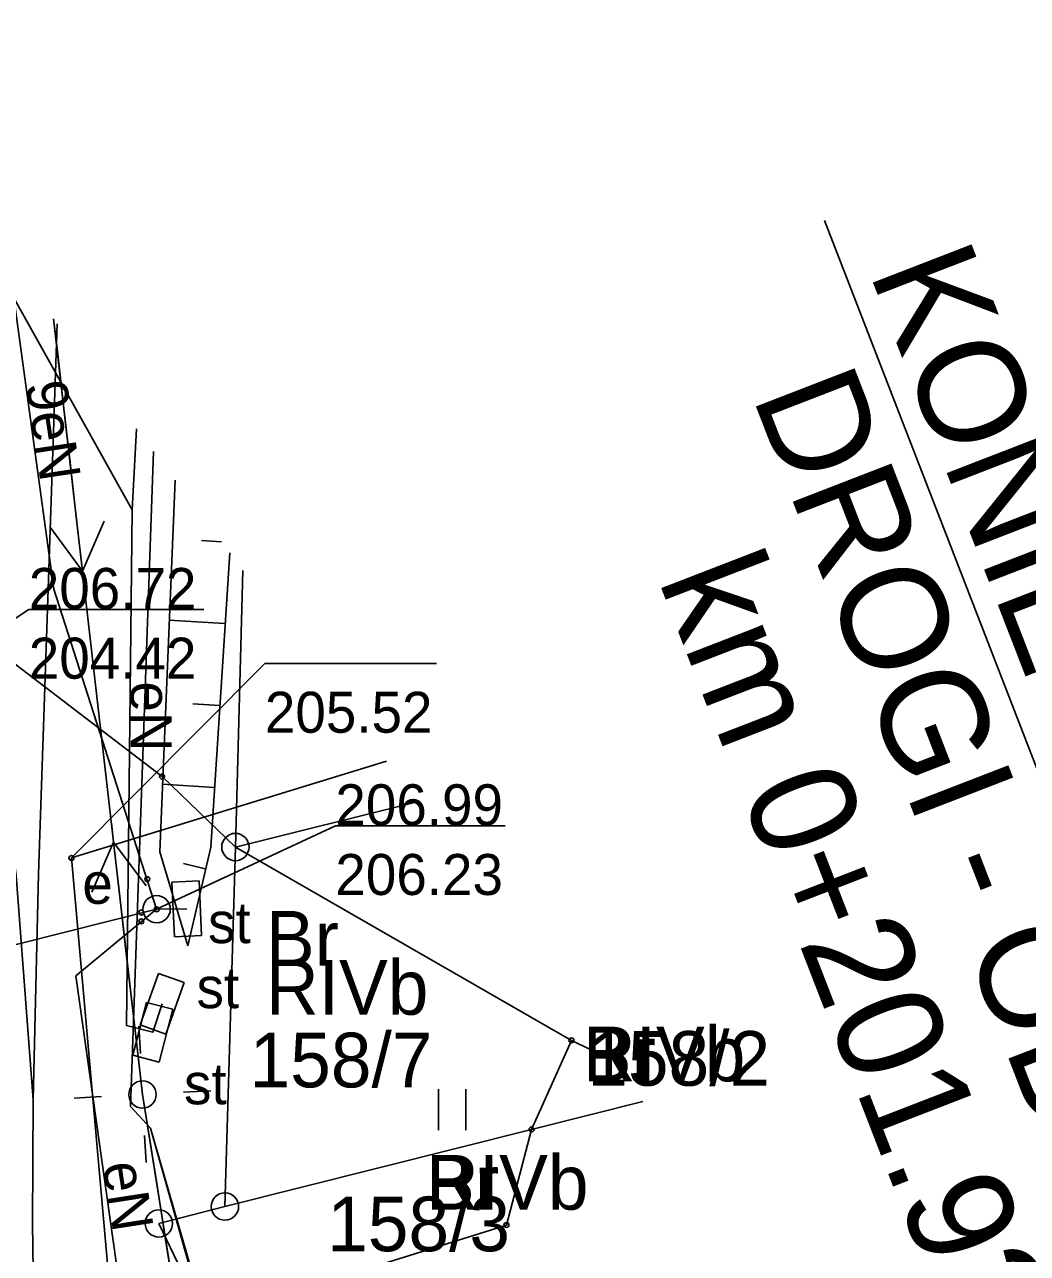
# Model space of a CAD drawing. Extents: x 6512606 to 6513006, y 6022524 to 6022728.
# Drawn here: x 6512853.97 to 6512872.32, y 6022634.38 to 6022656.88 of the extents above; entities that cross this region are included whole.
import ezdxf

# ---------------------------------------------------------------- set-up
doc = ezdxf.new("R2010")
doc.units = 0
for name, color, linetype in [('202-punkt graniczny', 7, 'Continuous'), ('203-punkt graniczny', 7, 'Continuous'), ('209-oznaczenie konturu klasyfikacyjnego', 7, 'Continuous'), ('210-oznaczenie konturu użytku gruntowego', 7, 'Continuous'), ('211-numer działki ewidencyjnej', 7, 'Continuous'), ('217-kontur klasyfikacyjny', 7, 'Continuous'), ('218-kontur użytku gruntowego', 7, 'Continuous'), ('219-działka ewidencyjna', 7, 'Continuous'), ('4', 7, 'Continuous'), ('820-Skarpa nieumocniona', 7, 'Continuous'), ('823-Szczyt skarpy nieumocninej', 7, 'Continuous'), ('824-Podnóże skarpy nieumocninej', 7, 'Continuous'), ('940-Trawnik symb. poj.', 7, 'Continuous'), ('chodnik (powierzchnia)', 7, 'Continuous'), ('Default', 7, 'Continuous'), ('krawężnik (linia)', 7, 'Continuous'), ('latarnia na słupie lub maszcie (punkt)', 7, 'Continuous'), ('maxp_opisy', 7, 'Continuous'), ('ogrodzenie trwałe (linia)', 7, 'Continuous'), ('przewód elektroenergetyczny (linia)', 7, 'Continuous'), ('przewód elektroenergetyczny (linia)-Atr1', 7, 'Continuous'), ('przewód elektroenergetyczny niskiego napięcia (linia)', 7, 'Continuous'), ('przewód elektroenergetyczny niskiego napięcia (linia) - symbol', 7, 'Continuous'), ('przewód gazowy (linia)', 7, 'Continuous'), ('punkt o określonej wysokości (sieć ciepłownicza)-Atr2', 7, 'Continuous'), ('punkt o określonej wysokości (sieć ciepłownicza)-Atr3', 7, 'Continuous'), ('punkt o określonej wysokości (sieć elektroenergetyczna)', 7, 'Continuous'), ('punkt o określonej wysokości (sieć elektroenergetyczna)-Atr2', 7, 'Continuous'), ('punkt o określonej wysokości (sieć elektroenergetyczna)-Atr3', 7, 'Continuous'), ('punkt o określonej wysokości (sieć gazowa)', 7, 'Continuous'), ('punkt o określonej wysokości (sieć gazowa)-Atr2', 7, 'Continuous'), ('punkt o określonej wysokości (sieć gazowa)-Atr3', 7, 'Continuous'), ('szafa elektroenergetyczna (punkt)', 7, 'Continuous'), ('szafa elektroenergetyczna (punkt)-Atr17', 7, 'Continuous'), ('słup (punkt)', 7, 'Continuous'), ('właz okrągły - siec elektroenergetyczna (punkt)', 7, 'Continuous'), ('właz okrągły - siec elektroenergetyczna (punkt)-Atr17', 7, 'Continuous')]:
    doc.layers.add(name, color=color, linetype=linetype)

# ---------------------------------------------------------------- blocks, each defined once
blk = doc.blocks.new('203')
at = {"layer": 'Default'}
blk.add_circle((0, 0), 0.45, dxfattribs=at)
blk = doc.blocks.new('202')
at = {"layer": 'Default'}
blk.add_circle((0, 0), 2.5, dxfattribs=at)
blk = doc.blocks.new('940P')
at = {"layer": 'Default'}
for p, q in [((-2.5, -3.75), (-2.5, 3.75)), ((2.5, -3.75), (2.5, 3.75))]:
    blk.add_line(p, q, dxfattribs=at)
blk = doc.blocks.new('US18')
at = {"layer": 'Default'}
for p, q in [((-5, -2.5), (-5, 2.5)), ((-5, 2.5), (5, 2.5)), ((5, -2.5), (5, 2.5)), ((-5, -2.5), (5, -2.5))]:
    blk.add_line(p, q, dxfattribs=at)
blk = doc.blocks.new('PW01')
at = {"layer": 'Default'}
blk.add_circle((0, 0), 0.45, dxfattribs=at)
blk = doc.blocks.new('US22')
at = {"layer": 'Default'}
blk.add_circle((0, 0), 2.5, dxfattribs=at)
blk = doc.blocks.new('PE04')
at = {"layer": 'Default'}
for p, q in [((46.5, 0), (37.84, 5)), ((6.5, 0), (0, 0)), ((6.5, 0), (16.5, 0)), ((16.5, 0), (26.5, 0)), ((26.5, 0), (36.5, 0)), ((36.5, 0), (46.5, 0)), ((46.5, 0), (37.84, -5)), ((46.5, 0), (50, 0))]:
    blk.add_line(p, q, dxfattribs=at)
blk = doc.blocks.new('SM04')
at = {"layer": 'Default'}
blk.add_circle((0, 0), 2.5, dxfattribs=at)
blk = doc.blocks.new('SM011')
at = {"layer": 'Default'}
for p, q in [((-5.3, 5.31), (-8.83, 8.84)), ((5.31, 5.31), (8.84, 8.84)), ((-5.3, -5.3), (-8.83, -8.83)), ((5.31, -5.3), (8.84, -8.83))]:
    blk.add_line(p, q, dxfattribs=at)

msp = doc.modelspace()

# ---------------------------------------------------------------- linework, layer by layer
at = {"layer": '217-kontur klasyfikacyjny'}
for points in [[(6512857.83, 6022641.82), (6512857.64, 6022635.24)], [(6512863.98, 6022638.28), (6512857.83, 6022641.82)], [(6512863.98, 6022638.28), (6512863.25, 6022636.65)], [(6512863.25, 6022636.65), (6512863.98, 6022638.28)], [(6512864.702, 6022637.935), (6512863.98, 6022638.28)], [(6512865.286, 6022637.159), (6512863.25, 6022636.65)], [(6512863.25, 6022636.65), (6512865.286, 6022637.159)], [(6512863.25, 6022636.65), (6512857.64, 6022635.24)], [(6512857.64, 6022635.24), (6512863.25, 6022636.65)], [(6512863.25, 6022636.65), (6512862.79, 6022634.9)], [(6512862.79, 6022634.9), (6512863.25, 6022636.65)], [(6512857.64, 6022635.24), (6512856.43, 6022634.93)], [(6512856.43, 6022634.93), (6512857.27, 6022633.17)], [(6512862.79, 6022634.9), (6512857.27, 6022633.17)], [(6512857.27, 6022633.17), (6512862.79, 6022634.9)]]:
    msp.add_lwpolyline(points, dxfattribs=at)
at = {"layer": '218-kontur użytku gruntowego'}
for points in [[(6512838.55, 6022656.82), (6512856.49, 6022643.11)], [(6512856.49, 6022643.11), (6512838.55, 6022656.82)], [(6512857.83, 6022641.82), (6512857.969, 6022646.885)], [(6512857.969, 6022646.885), (6512857.83, 6022641.82)], [(6512856.49, 6022643.11), (6512857.83, 6022641.82)], [(6512857.83, 6022641.82), (6512856.49, 6022643.11)], [(6512857.64, 6022635.24), (6512857.83, 6022641.82)], [(6512857.83, 6022641.82), (6512857.64, 6022635.24)], [(6512863.98, 6022638.28), (6512857.83, 6022641.82)], [(6512857.83, 6022641.82), (6512863.98, 6022638.28)], [(6512863.98, 6022638.28), (6512863.25, 6022636.65)], [(6512863.25, 6022636.65), (6512863.98, 6022638.28)], [(6512864.702, 6022637.935), (6512863.98, 6022638.28)], [(6512863.98, 6022638.28), (6512864.702, 6022637.935)], [(6512865.286, 6022637.159), (6512863.25, 6022636.65)], [(6512863.25, 6022636.65), (6512865.286, 6022637.159)], [(6512863.25, 6022636.65), (6512857.64, 6022635.24)], [(6512857.64, 6022635.24), (6512863.25, 6022636.65)], [(6512863.25, 6022636.65), (6512862.79, 6022634.9)], [(6512862.79, 6022634.9), (6512863.25, 6022636.65)], [(6512856.43, 6022634.93), (6512857.64, 6022635.24)], [(6512857.64, 6022635.24), (6512856.43, 6022634.93)], [(6512857.27, 6022633.17), (6512856.43, 6022634.93)], [(6512856.43, 6022634.93), (6512857.27, 6022633.17)], [(6512862.79, 6022634.9), (6512857.27, 6022633.17)], [(6512857.27, 6022633.17), (6512862.79, 6022634.9)]]:
    msp.add_lwpolyline(points, dxfattribs=at)
at = {"layer": '219-działka ewidencyjna'}
for points in [[(6512856.49, 6022643.11), (6512838.55, 6022656.82)], [(6512857.83, 6022641.82), (6512857.969, 6022646.885)], [(6512857.83, 6022641.82), (6512856.49, 6022643.11)], [(6512857.83, 6022641.82), (6512861.155, 6022642.649)], [(6512857.83, 6022641.82), (6512857.64, 6022635.24)], [(6512863.98, 6022638.28), (6512857.83, 6022641.82)], [(6512863.98, 6022638.28), (6512863.25, 6022636.65)], [(6512864.702, 6022637.935), (6512863.98, 6022638.28)], [(6512865.286, 6022637.159), (6512863.25, 6022636.65)], [(6512863.25, 6022636.65), (6512857.64, 6022635.24)], [(6512863.25, 6022636.65), (6512862.79, 6022634.9)], [(6512856.43, 6022634.93), (6512857.64, 6022635.24)], [(6512857.27, 6022633.17), (6512856.43, 6022634.93)], [(6512862.79, 6022634.9), (6512857.27, 6022633.17)]]:
    msp.add_lwpolyline(points, dxfattribs=at)
at = {"layer": '4'}
for points in [[(6512856.49, 6022643.11), (6512838.55, 6022656.82)], [(6512857.83, 6022641.82), (6512857.969, 6022646.885)], [(6512857.83, 6022641.82), (6512856.49, 6022643.11)], [(6512857.83, 6022641.82), (6512861.155, 6022642.649)], [(6512857.83, 6022641.82), (6512857.64, 6022635.24)], [(6512863.98, 6022638.28), (6512857.83, 6022641.82)], [(6512863.98, 6022638.28), (6512863.25, 6022636.65)], [(6512864.702, 6022637.935), (6512863.98, 6022638.28)], [(6512865.286, 6022637.159), (6512863.25, 6022636.65)], [(6512863.25, 6022636.65), (6512857.64, 6022635.24)], [(6512863.25, 6022636.65), (6512862.79, 6022634.9)], [(6512856.43, 6022634.93), (6512857.64, 6022635.24)], [(6512857.27, 6022633.17), (6512856.43, 6022634.93)], [(6512862.79, 6022634.9), (6512857.27, 6022633.17)]]:
    msp.add_lwpolyline(points, dxfattribs=at)
at = {"layer": '820-Skarpa nieumocniona'}
for p, q in [((6512857.575, 6022647.409), (6512857.21, 6022647.43)), ((6512857.64, 6022645.91), (6512856.61, 6022645.97)), ((6512857.54, 6022644.41), (6512857.05, 6022644.44)), ((6512857.45, 6022642.91), (6512856.49, 6022642.97)), ((6512857.28, 6022641.42), (6512856.88, 6022641.52))]:
    msp.add_line(p, q, dxfattribs=at)
at = {"layer": '823-Szczyt skarpy nieumocninej'}
msp.add_lwpolyline([(6512857.727, 6022647.206), (6512857.38, 6022641.82), (6512856.96, 6022640.01)], dxfattribs=at)
at = {"layer": '824-Podnóże skarpy nieumocninej'}
msp.add_lwpolyline([(6512856.728, 6022648.534), (6512856.45, 6022641.73), (6512856.96, 6022640.01)], dxfattribs=at)
at = {"layer": 'chodnik (powierzchnia)'}
for points in [[(6512852.028, 6022654.782), (6512852.46, 6022651.24), (6512853.17, 6022646.34), (6512853.82, 6022641.3), (6512854.13, 6022637.19), (6512854.23, 6022641.33)], [(6512854.23, 6022641.33), (6512854.572, 6022651.4)], [(6512856.331, 6022649.061), (6512855.91, 6022637.07), (6512856.28, 6022636.67), (6512857.18, 6022633.47)]]:
    msp.add_lwpolyline(points, dxfattribs=at)
at = {"layer": 'krawężnik (linia)'}
msp.add_lwpolyline([(6512854.13, 6022634.06), (6512854.12, 6022634.93), (6512854.13, 6022637.19), (6512853.82, 6022641.3), (6512853.17, 6022646.34), (6512852.46, 6022651.24), (6512852.028, 6022654.782)], dxfattribs=at)
at = {"layer": 'maxp_opisy'}
msp.add_lwpolyline([(6512856.121, 6022593.53), (6512879.345, 6022625.572), (6512868.61, 6022653.292)], dxfattribs=at)
at = {"layer": 'ogrodzenie trwałe (linia)'}
msp.add_lwpolyline([(6512859.49, 6022628.57), (6512858.5, 6022630.69), (6512857.21, 6022633.44), (6512856.28, 6022636.67)], dxfattribs=at)
at = {"layer": 'przewód elektroenergetyczny (linia)'}
for points in [[(6512856.32, 6022638.43), (6512855.84, 6022638.55), (6512855.94, 6022647.99), (6512853.31, 6022652.69), (6512841.05, 6022650.73), (6512840.36, 6022658.31), (6512832.38, 6022663.33)], [(6512856.39, 6022640.68), (6512854.51, 6022646.54), (6512853.677, 6022652.59)], [(6512856.022, 6022649.473), (6512855.94, 6022647.99), (6512855.84, 6022638.55), (6512856.32, 6022638.43), (6512856.49, 6022638.95)], [(6512856.39, 6022640.68), (6512852.99, 6022639.83), (6512851.54, 6022639.74), (6512850.48, 6022647.67), (6512851.95, 6022647.83), (6512852.99, 6022639.83)], [(6512856.39, 6022640.68), (6512852.99, 6022639.83), (6512851.54, 6022639.74), (6512849.57, 6022639.5), (6512850.08, 6022635.56), (6512848.6, 6022635.43), (6512846.66, 6022647.32), (6512848.47, 6022647.49), (6512849.57, 6022639.5)], [(6512856.39, 6022640.68), (6512854.91, 6022639.46), (6512857.58, 6022620.49)], [(6512856.39, 6022640.68), (6512856.94, 6022640.69)]]:
    msp.add_lwpolyline(points, dxfattribs=at)
at = {"layer": 'przewód elektroenergetyczny niskiego napięcia (linia)'}
for points in [[(6512856.13, 6022637.29), (6512854.505, 6022651.489)], [(6512854.505, 6022651.489), (6512856.13, 6022637.29)], [(6512861.56, 6022603.29), (6512856.13, 6022637.29)]]:
    msp.add_lwpolyline(points, dxfattribs=at)
at = {"layer": 'przewód gazowy (linia)'}
for points in [[(6512854.83, 6022641.62), (6512860.596, 6022643.393)], [(6512871.862, 6022571.535), (6512870.29, 6022578.43), (6512869.58, 6022581.52), (6512865.64, 6022595.96), (6512860.06, 6022617.51), (6512858.39, 6022625.33), (6512855.49, 6022634.19), (6512854.83, 6022641.62)]]:
    msp.add_lwpolyline(points, dxfattribs=at)
at = {"layer": 'punkt o określonej wysokości (sieć ciepłownicza)-Atr2'}
msp.add_lwpolyline([(6512851.41, 6022644.43), (6512854.05, 6022646.17), (6512857.254, 6022646.17)], dxfattribs=at)
at = {"layer": 'punkt o określonej wysokości (sieć elektroenergetyczna)-Atr2'}
msp.add_lwpolyline([(6512856.39, 6022640.68), (6512859.66, 6022642.21), (6512862.769, 6022642.21)], dxfattribs=at)
at = {"layer": 'punkt o określonej wysokości (sieć gazowa)-Atr2'}
msp.add_lwpolyline([(6512854.83, 6022641.62), (6512858.37, 6022645.18), (6512861.511, 6022645.18)], dxfattribs=at)

# ---------------------------------------------------------------- block references
at = {"layer": '202-punkt graniczny', "xscale": 0.1, "yscale": 0.10000000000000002}
for p in [(6512857.83, 6022641.82), (6512857.64, 6022635.24), (6512856.43, 6022634.93)]:
    msp.add_blockref('202', p, dxfattribs=at)
at = {"layer": '203-punkt graniczny', "xscale": 0.1, "yscale": 0.10000000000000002}
for p in [(6512856.49, 6022643.11), (6512863.98, 6022638.28), (6512863.25, 6022636.65), (6512862.79, 6022634.9)]:
    msp.add_blockref('203', p, dxfattribs=at)
at = {"layer": '940-Trawnik symb. poj.', "xscale": 0.1, "yscale": 0.10000000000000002, "rotation": 180}
msp.add_blockref('940P', (6512861.8, 6022637.01), dxfattribs=at)
at = {"layer": 'latarnia na słupie lub maszcie (punkt)', "xscale": 0.10000000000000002, "yscale": 0.1, "rotation": -42.018}
msp.add_blockref('SM011', (6512856.13, 6022637.29), dxfattribs=at)
at = {"layer": 'przewód elektroenergetyczny niskiego napięcia (linia) - symbol'}
for p, xscale, yscale, rotation in [((6512854.505, 6022651.489), 0.10000000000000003, 0.1, -83.47099999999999), ((6512856.13, 6022637.29), 0.10000000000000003, 0.1, 96.529), ((6512856.13, 6022637.29), 0.1, 0.09999999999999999, -80.92599999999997)]:
    msp.add_blockref('PE04', p, dxfattribs=dict(at, xscale=xscale, yscale=yscale, rotation=rotation))
at = {"layer": 'punkt o określonej wysokości (sieć elektroenergetyczna)', "xscale": 0.1}
for p, yscale, rotation in [((6512856.22, 6022641.23), 0.09999999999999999, -71.418), ((6512856.11, 6022640.62), 0.10000000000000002, 14.868), ((6512856.39, 6022640.68), 0.10000000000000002, -90), ((6512856.11, 6022640.46), 0.10000000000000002, 40.342)]:
    msp.add_blockref('PW01', p, dxfattribs=dict(at, yscale=yscale, rotation=rotation))
at = {"layer": 'punkt o określonej wysokości (sieć gazowa)', "xscale": 0.1, "yscale": 0.10000000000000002}
msp.add_blockref('PW01', (6512854.83, 6022641.62), dxfattribs=at)
at = {"layer": 'szafa elektroenergetyczna (punkt)'}
for p, xscale, yscale, rotation in [((6512856.94, 6022640.69), 0.1, 0.09999999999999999, 92.726), ((6512856.49, 6022638.95), 0.10000000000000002, 0.1, 70.34600000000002), ((6512856.32, 6022638.43), 0.1, 0.10000000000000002, -104.381)]:
    msp.add_blockref('US18', p, dxfattribs=dict(at, xscale=xscale, yscale=yscale, rotation=rotation))
at = {"layer": 'słup (punkt)', "xscale": 0.1, "yscale": 0.10000000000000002}
msp.add_blockref('SM04', (6512856.13, 6022637.29), dxfattribs=at)
at = {"layer": 'właz okrągły - siec elektroenergetyczna (punkt)', "xscale": 0.1, "yscale": 0.10000000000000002, "rotation": -90}
msp.add_blockref('US22', (6512856.39, 6022640.68), dxfattribs=at)

# ---------------------------------------------------------------- texts
at = {"layer": '209-oznaczenie konturu klasyfikacyjnego'}
for p in [(6512858.39, 6022638.75), (6512864.19, 6022637.53), (6512861.32, 6022635.18)]:
    msp.add_text('RIVb', height=1, dxfattribs=at).set_placement(p)
at = {"layer": '210-oznaczenie konturu użytku gruntowego'}
for p in [(6512858.39, 6022639.65), (6512864.19, 6022637.53), (6512861.32, 6022635.18)]:
    msp.add_text('Br', height=1, dxfattribs=at).set_placement(p)
at = {"layer": '211-numer działki ewidencyjnej'}
for s, p in [('158/7', (6512858.09, 6022637.42)), ('158/2', (6512864.27, 6022637.45)), ('158/3', (6512859.51, 6022634.42))]:
    msp.add_text(s, height=1, dxfattribs=at).set_placement(p)
at = {"layer": '4'}
for s, p in [('158/7', (6512858.09, 6022637.42)), ('158/2', (6512864.27, 6022637.45)), ('158/3', (6512859.51, 6022634.42))]:
    msp.add_text(s, height=1, dxfattribs=at).set_placement(p)
at = {"layer": 'maxp_opisy'}
for s, p in [('KONIEC BUDOWY', (6512869.42, 6022652.352)), ('DROGI - ODC. A', (6512867.279, 6022650.083)), ('km 0+201.92', (6512865.56, 6022646.723))]:
    msp.add_text(s, height=1.936, rotation=291.169, dxfattribs=at).set_placement(p)
at = {"layer": 'przewód elektroenergetyczny (linia)-Atr1'}
for s, rotation, p in [('9eN', 278.639, (6512853.99, 6022650.3)), ('eN', 270.182, (6512855.91, 6022644.85)), ('eN', 278.799, (6512855.4, 6022636.01))]:
    msp.add_text(s, height=0.75, rotation=rotation, dxfattribs=at).set_placement(p)
at = {"layer": 'punkt o określonej wysokości (sieć ciepłownicza)-Atr2'}
msp.add_text('206.72', height=0.75, dxfattribs=at).set_placement((6512854.05, 6022646.178))
at = {"layer": 'punkt o określonej wysokości (sieć ciepłownicza)-Atr3'}
msp.add_text('204.42', height=0.75, dxfattribs=at).set_placement((6512854.05, 6022644.902))
at = {"layer": 'punkt o określonej wysokości (sieć elektroenergetyczna)-Atr2'}
msp.add_text('206.99', height=0.75, dxfattribs=at).set_placement((6512859.66, 6022642.218))
at = {"layer": 'punkt o określonej wysokości (sieć elektroenergetyczna)-Atr3'}
msp.add_text('206.23', height=0.75, dxfattribs=at).set_placement((6512859.66, 6022640.942))
at = {"layer": 'punkt o określonej wysokości (sieć gazowa)-Atr3'}
msp.add_text('205.52', height=0.75, dxfattribs=at).set_placement((6512858.37, 6022643.912))
at = {"layer": 'szafa elektroenergetyczna (punkt)-Atr17'}
for p in [(6512857.33, 6022640.06), (6512857.12, 6022638.87), (6512856.89, 6022637.11)]:
    msp.add_text('st', height=0.75, dxfattribs=at).set_placement(p)
at = {"layer": 'właz okrągły - siec elektroenergetyczna (punkt)-Atr17'}
msp.add_text('e', height=0.75, dxfattribs=at).set_placement((6512855.03, 6022640.78))

doc.saveas('drawing.dxf')
